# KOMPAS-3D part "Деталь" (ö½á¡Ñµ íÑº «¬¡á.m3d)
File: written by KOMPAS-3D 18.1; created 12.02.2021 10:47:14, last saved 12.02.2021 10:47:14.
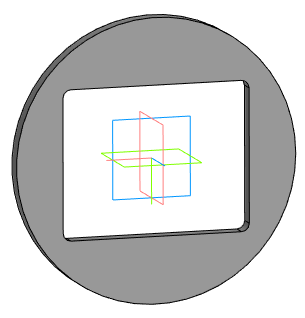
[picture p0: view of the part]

Document properties: Полное имя файла: C:\GoogleDrive\НИР\ИКИ\Компас\Фланец без окна.m3d

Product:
- Part/product: Деталь
    Масса: 1.10521

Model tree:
1. Эскиз:1
2. Элемент выдавливания:1
     Расстояние 1 = 10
